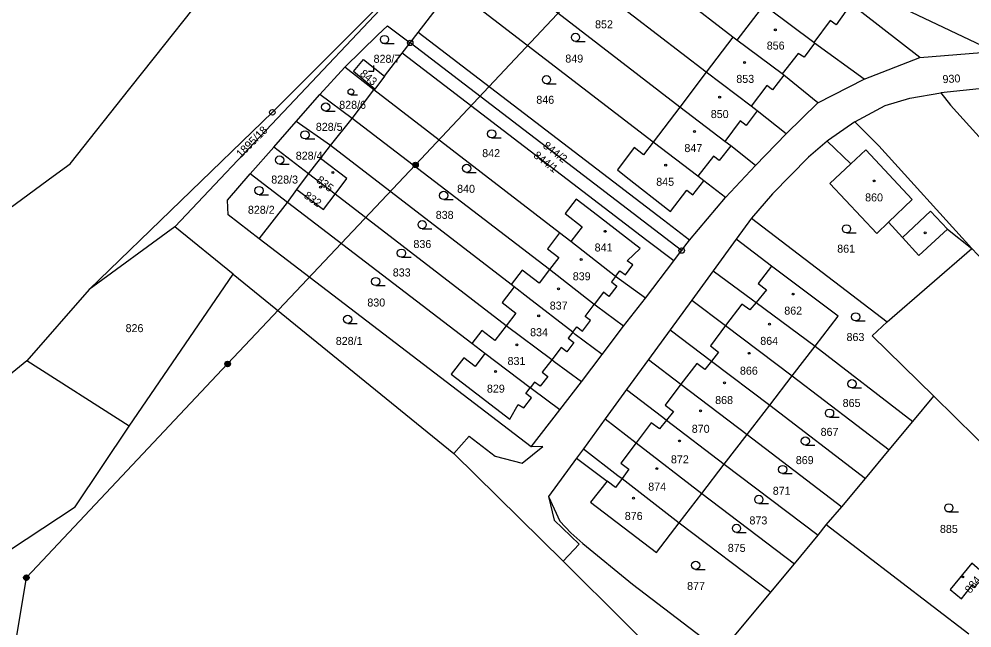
# Model space of a CAD drawing. Extents: x -587171 to -555306, y -1167727 to -1074732.
# Drawn here: x -560459.2 to -560285.3, y -1077700.6 to -1077589.4 of the extents above; entities that cross this region are included whole.
import ezdxf

# ---------------------------------------------------------------- set-up
doc = ezdxf.new("R2010")
doc.units = 0
for name, color, linetype in [('Hranice parcel', 7, 'Continuous'), ('Parcelní čísla', 7, 'Continuous'), ('Poz předměty', 7, 'Continuous'), ('Vnitřní kresba', 7, 'Continuous'), ('Značky bodu BP', 7, 'Continuous'), ('Značky budov', 7, 'Continuous'), ('Značky kultur', 7, 'Continuous')]:
    doc.layers.add(name, color=color, linetype=linetype)

msp = doc.modelspace()

# ---------------------------------------------------------------- linework, layer by layer
at = {"layer": 'Hranice parcel'}
for p, q in [((-560328.96, -1077592.74), (-560364.28, -1077565.15)), ((-560375.85, -1077569.17), (-560430.81, -1077627.37)), ((-560333.83, -1077599.11), (-560365.63, -1077574.69)), ((-560338.65, -1077605.51), (-560374.99, -1077577.45)), ((-560294.85, -1077596.46), (-560316.6, -1077579.54)), ((-560386.37, -1077591.88), (-560380.16, -1077583.81)), ((-560434.49, -1077596.45), (-560425.52, -1077585.14)), ((-560343.49, -1077611.88), (-560376, -1077586.97)), ((-560323.4, -1077586.94), (-560328.26, -1077593.3)), ((-560399.76, -1077598.23), (-560393.77, -1077592.33)), ((-560387.83, -1077593.78), (-560386.37, -1077591.88)), ((-560328.96, -1077592.74), (-560333.83, -1077599.11)), ((-560328.26, -1077593.3), (-560328.96, -1077592.74)), ((-560389.29, -1077595.68), (-560387.83, -1077593.78)), ((-560338.32, -1077631.68), (-560387.83, -1077593.78)), ((-560438.98, -1077602.1), (-560434.49, -1077596.45)), ((-560392.51, -1077599.88), (-560389.29, -1077595.68)), ((-560305.04, -1077600.41), (-560294.85, -1077596.46)), ((-560294.85, -1077596.46), (-560281.21, -1077595.33)), ((-560404.3, -1077603.17), (-560399.76, -1077598.23)), ((-560394.49, -1077602.37), (-560399.76, -1077598.23)), ((-560392.51, -1077599.88), (-560394.27, -1077602.21)), ((-560333.83, -1077599.11), (-560338.65, -1077605.51)), ((-560313.48, -1077604.7), (-560305.04, -1077600.41)), ((-560394.49, -1077602.37), (-560394.27, -1077602.21)), ((-560282.9, -1077602.07), (-560291.02, -1077602.87)), ((-560408.64, -1077608.12), (-560404.3, -1077603.17)), ((-560398.45, -1077607.55), (-560404.3, -1077603.17)), ((-560398.45, -1077607.55), (-560394.49, -1077602.37)), ((-560360.58, -1077628.44), (-560394.49, -1077602.37)), ((-560338.65, -1077605.51), (-560343.49, -1077611.88)), ((-560319.23, -1077610.35), (-560313.48, -1077604.7)), ((-560412.73, -1077612.8), (-560408.64, -1077608.12)), ((-560402.41, -1077612.48), (-560408.64, -1077608.12)), ((-560402.41, -1077612.48), (-560398.45, -1077607.55)), ((-560362.45, -1077635.15), (-560398.45, -1077607.55)), ((-560324.82, -1077616.15), (-560319.23, -1077610.35)), ((-560404.23, -1077614.85), (-560402.41, -1077612.48)), ((-560369.4, -1077637.89), (-560402.41, -1077612.48)), ((-560417.03, -1077617.7), (-560412.73, -1077612.8)), ((-560406.38, -1077617.66), (-560412.73, -1077612.8)), ((-560406.38, -1077617.66), (-560404.23, -1077614.85)), ((-560330.32, -1077621.99), (-560324.82, -1077616.15)), ((-560421.2, -1077622.46), (-560417.03, -1077617.7)), ((-560410.21, -1077622.9), (-560417.03, -1077617.7)), ((-560408.5, -1077620.55), (-560406.38, -1077617.66)), ((-560401.53, -1077621.39), (-560406.38, -1077617.66)), ((-560471.23, -1077631.45), (-560452.96, -1077618.09)), ((-560330.32, -1077621.99), (-560334.28, -1077618.93)), ((-560410.21, -1077622.9), (-560408.5, -1077620.55)), ((-560370.31, -1077645.39), (-560401.53, -1077621.39)), ((-560415.38, -1077629.52), (-560410.21, -1077622.9)), ((-560376.61, -1077648.66), (-560410.21, -1077622.9)), ((-560336.89, -1077629.78), (-560330.32, -1077621.99)), ((-560325.56, -1077625.77), (-560328.38, -1077629.63)), ((-560325.56, -1077625.77), (-560300.82, -1077644.66)), ((-560430.81, -1077627.37), (-560446.42, -1077638.81)), ((-560420.13, -1077636.01), (-560430.81, -1077627.37)), ((-560365.79, -1077667.51), (-560415.38, -1077629.52)), ((-560358.52, -1077630.03), (-560360.58, -1077628.44)), ((-560350.37, -1077636.41), (-560358.52, -1077630.03)), ((-560338.32, -1077631.68), (-560336.89, -1077629.78)), ((-560328.38, -1077629.63), (-560332.57, -1077635.37)), ((-560339.72, -1077633.58), (-560338.32, -1077631.68)), ((-560300.82, -1077644.66), (-560285.36, -1077631.28)), ((-560344.89, -1077640.37), (-560339.72, -1077633.58)), ((-560439.14, -1077663.72), (-560420.13, -1077636.01)), ((-560420.13, -1077636.01), (-560379.89, -1077668.73)), ((-560344.89, -1077640.37), (-560350.37, -1077636.41)), ((-560332.57, -1077635.37), (-560336.47, -1077640.72)), ((-560368.85, -1077638.32), (-560369.4, -1077637.89)), ((-560446.42, -1077638.81), (-560457.78, -1077651.79)), ((-560348.9, -1077645.47), (-560344.89, -1077640.37)), ((-560336.47, -1077640.72), (-560340.42, -1077646.14)), ((-560352.79, -1077650.67), (-560348.9, -1077645.47)), ((-560340.42, -1077646.14), (-560344.39, -1077651.58)), ((-560374.22, -1077650.49), (-560376.61, -1077648.66)), ((-560318.12, -1077654.53), (-560313.97, -1077649.13)), ((-560313.97, -1077649.13), (-560296.15, -1077662.88)), ((-560365.96, -1077656.73), (-560374.22, -1077650.49)), ((-560356.61, -1077655.66), (-560352.79, -1077650.67)), ((-560439.14, -1077663.72), (-560457.78, -1077651.79)), ((-560344.39, -1077651.58), (-560348.35, -1077657.02)), ((-560360.53, -1077660.72), (-560356.61, -1077655.66)), ((-560322.24, -1077659.89), (-560318.12, -1077654.53)), ((-560318.12, -1077654.53), (-560300.47, -1077668.07)), ((-560348.35, -1077657.02), (-560352.28, -1077662.4)), ((-560296.15, -1077662.88), (-560292.32, -1077658.28)), ((-560365.79, -1077667.51), (-560360.53, -1077660.72)), ((-560326.37, -1077665.27), (-560322.24, -1077659.89)), ((-560322.24, -1077659.89), (-560304.79, -1077673.26)), ((-560352.28, -1077662.4), (-560356.25, -1077667.84)), ((-560300.47, -1077668.07), (-560296.15, -1077662.88)), ((-560330.53, -1077670.68), (-560326.37, -1077665.27)), ((-560326.37, -1077665.27), (-560309.1, -1077678.45)), ((-560356.25, -1077667.84), (-560357.49, -1077669.54)), ((-560304.79, -1077673.26), (-560300.47, -1077668.07)), ((-560379.89, -1077668.73), (-560359.92, -1077688.39)), ((-560357.49, -1077669.54), (-560362.63, -1077676.58)), ((-560334.63, -1077676), (-560330.53, -1077670.68)), ((-560330.53, -1077670.68), (-560313.42, -1077683.64)), ((-560309.1, -1077678.45), (-560304.79, -1077673.26)), ((-560338.75, -1077681.37), (-560334.63, -1077676)), ((-560334.63, -1077676), (-560317.73, -1077688.83)), ((-560311.93, -1077681.72), (-560309.1, -1077678.45)), ((-560338.75, -1077681.37), (-560322.05, -1077694.02)), ((-560313.42, -1077683.64), (-560311.93, -1077681.72)), ((-560285.91, -1077701.68), (-560311.93, -1077681.72)), ((-560317.73, -1077688.83), (-560313.42, -1077683.64)), ((-560322.05, -1077694.02), (-560317.73, -1077688.83)), ((-560331.1, -1077704.9), (-560322.05, -1077694.02))]:
    msp.add_line(p, q, dxfattribs=at)
for points in [[(-560375.85, -1077569.17), (-560412.99, -1077606.45), (-560446.42, -1077638.81)], [(-560312.4, -1077568.89), (-560315.15, -1077573.69), (-560305.39, -1077581.46), (-560297.55, -1077587.6), (-560281.21, -1077595.33)], [(-560305.04, -1077600.41), (-560314.06, -1077593.83), (-560314.2, -1077593.72), (-560322.61, -1077587.46)], [(-560393.77, -1077592.33), (-560391.98, -1077590.67), (-560387.83, -1077593.78)], [(-560336.89, -1077629.78), (-560341.64, -1077626.13), (-560386.37, -1077591.88)], [(-560313.48, -1077604.7), (-560319.68, -1077599.65), (-560319.95, -1077599.45), (-560328.26, -1077593.3)], [(-560394.27, -1077602.21), (-560398.2, -1077599.02), (-560396.35, -1077596.84), (-560392.51, -1077599.88)], [(-560339.72, -1077633.58), (-560344.65, -1077629.82), (-560389.29, -1077595.68)], [(-560319.23, -1077610.35), (-560324.55, -1077606.15), (-560325.65, -1077605.33), (-560333.83, -1077599.11)], [(-560452.96, -1077618.09), (-560449.89, -1077615.85), (-560438.98, -1077602.1)], [(-560306.74, -1077608.21), (-560301.16, -1077605.22), (-560296.7, -1077603.88), (-560291.02, -1077602.87)], [(-560291.02, -1077602.87), (-560289.24, -1077605.17), (-560274.76, -1077621.16), (-560270.12, -1077616.52)], [(-560324.82, -1077616.15), (-560329.36, -1077612.58), (-560330.46, -1077611.76), (-560338.65, -1077605.51)], [(-560306.74, -1077608.21), (-560311.54, -1077611.52), (-560311.77, -1077611.71)], [(-560285.36, -1077631.28), (-560302.35, -1077612.59), (-560306.74, -1077608.21)], [(-560343.49, -1077611.88), (-560345.29, -1077614.19), (-560346.96, -1077612.89), (-560350.02, -1077616.95), (-560348.41, -1077618.21), (-560340.34, -1077624.54), (-560337.38, -1077620.65), (-560336.25, -1077621.5), (-560334.28, -1077618.93)], [(-560334.28, -1077618.93), (-560335.35, -1077618.1), (-560343.49, -1077611.88)], [(-560311.77, -1077611.71), (-560315.2, -1077614.66), (-560321.76, -1077621.32), (-560325.56, -1077625.77)], [(-560311.77, -1077611.71), (-560307.44, -1077615.83), (-560311.29, -1077619.43), (-560302.73, -1077628.55), (-560300.57, -1077626.48), (-560298, -1077629.32), (-560295.01, -1077632.56), (-560289.83, -1077627.79), (-560285.36, -1077631.28)], [(-560401.53, -1077621.39), (-560399.42, -1077618.53), (-560404.23, -1077614.85)], [(-560408.5, -1077620.55), (-560403.64, -1077624.21), (-560401.53, -1077621.39)], [(-560415.38, -1077629.52), (-560421.06, -1077625.15), (-560421.2, -1077622.46)], [(-560350.37, -1077636.41), (-560349.58, -1077635.36), (-560348.58, -1077636.12), (-560347.22, -1077634.29), (-560348.25, -1077633.54), (-560345.86, -1077631.3), (-560354.43, -1077624.7), (-560357.56, -1077622.29), (-560359.58, -1077624.92), (-560356.44, -1077627.33), (-560358.52, -1077630.03)], [(-560360.58, -1077628.44), (-560362.77, -1077631.37), (-560360.74, -1077632.93), (-560362.45, -1077635.15)], [(-560313.97, -1077649.13), (-560309.75, -1077643.64), (-560321.91, -1077634.5), (-560328.38, -1077629.63)], [(-560281.82, -1077635.16), (-560283.33, -1077633.51), (-560285.36, -1077631.28)], [(-560362.45, -1077635.15), (-560364.34, -1077637.62), (-560367.4, -1077635.27), (-560369.4, -1077637.89)], [(-560348.9, -1077645.47), (-560353.88, -1077641.83), (-560354.28, -1077641.52), (-560362.45, -1077635.15)], [(-560332.57, -1077635.37), (-560325.38, -1077640.68), (-560324.74, -1077641.16), (-560313.97, -1077649.13)], [(-560368.85, -1077638.32), (-560371.04, -1077641.16), (-560368.54, -1077643.08), (-560370.31, -1077645.39)], [(-560352.79, -1077650.67), (-560357.73, -1077646.97), (-560358.19, -1077646.6), (-560366.35, -1077640.24), (-560368.85, -1077638.32)], [(-560336.47, -1077640.72), (-560330.3, -1077645.36), (-560318.12, -1077654.53)], [(-560370.31, -1077645.39), (-560372.39, -1077648.11), (-560374.78, -1077646.28), (-560376.61, -1077648.66)], [(-560356.61, -1077655.66), (-560361.56, -1077651.96), (-560362.01, -1077651.62), (-560370.31, -1077645.39)], [(-560292.32, -1077658.28), (-560303.56, -1077647.23), (-560300.82, -1077644.66)], [(-560340.42, -1077646.14), (-560332.85, -1077651.86), (-560322.24, -1077659.89)], [(-560374.22, -1077650.49), (-560376.01, -1077652.83), (-560378.08, -1077651.24), (-560380.39, -1077654.25), (-560378.32, -1077655.83), (-560369.68, -1077662.43), (-560368.13, -1077659.77), (-560367.08, -1077660.38), (-560365.72, -1077658.55), (-560366.75, -1077657.77), (-560365.96, -1077656.73)], [(-560457.78, -1077651.79), (-560466.53, -1077658.92), (-560480.72, -1077671.61), (-560494.34, -1077686.1), (-560508.9, -1077703.53)], [(-560344.39, -1077651.58), (-560338.46, -1077656.08), (-560326.37, -1077665.27)], [(-560360.53, -1077660.72), (-560365.51, -1077657.06), (-560365.96, -1077656.73)], [(-560348.35, -1077657.02), (-560341.74, -1077662.09), (-560341.05, -1077662.62), (-560330.53, -1077670.68)], [(-560237.94, -1077711.73), (-560238.65, -1077711.03), (-560292.32, -1077658.28)], [(-560352.28, -1077662.4), (-560346.63, -1077666.75), (-560334.63, -1077676)], [(-560498.51, -1077705.52), (-560481.85, -1077698.21), (-560474.04, -1077694.55), (-560466.89, -1077690.27), (-560448.98, -1077678.42), (-560439.14, -1077663.72)], [(-560379.89, -1077668.73), (-560377.06, -1077665.55), (-560372.31, -1077669.2), (-560367.44, -1077670.51), (-560363.63, -1077667.44), (-560365.79, -1077667.51)], [(-560356.25, -1077667.84), (-560349.94, -1077672.72), (-560349.19, -1077673.3), (-560338.75, -1077681.37)], [(-560357.49, -1077669.54), (-560351.9, -1077673.74), (-560354.93, -1077677.6), (-560342.93, -1077686.8), (-560338.75, -1077681.37)], [(-560362.63, -1077676.58), (-560360.56, -1077681.04), (-560358.52, -1077683.18), (-560356.35, -1077685.14), (-560347.27, -1077692.56), (-560331.1, -1077704.9)], [(-560362.63, -1077676.58), (-560361.55, -1077680.87), (-560357.03, -1077685.24), (-560359.92, -1077688.39)], [(-560359.92, -1077688.39), (-560336.97, -1077711.25), (-560277.37, -1077755.62)], [(-560284.85, -1077693.05), (-560282.89, -1077690.9), (-560285.37, -1077688.75), (-560289.35, -1077693.54), (-560287.27, -1077695.26), (-560285.22, -1077692.71), (-560284.85, -1077693.05)]]:
    msp.add_lwpolyline(points, dxfattribs=at)
at = {"layer": 'Poz předměty'}
for p, q in [((-560354.12, -1077581.15), (-560386.86, -1077616.04)), ((-560386.86, -1077616.04), (-560421.15, -1077652.37)), ((-560457.87, -1077691.37), (-560421.15, -1077652.37)), ((-560467.98, -1077753.51), (-560457.87, -1077691.37))]:
    msp.add_line(p, q, dxfattribs=at)
for centre, radius in [((-560386.86, -1077616.04), 0.5), ((-560386.86, -1077616.04), 0.4), ((-560386.86, -1077616.04), 0.3), ((-560386.86, -1077616.04), 0.2), ((-560386.86, -1077616.04), 0.1), ((-560421.15, -1077652.37), 0.5), ((-560421.15, -1077652.37), 0.5), ((-560421.15, -1077652.37), 0.4), ((-560421.15, -1077652.37), 0.4), ((-560421.15, -1077652.37), 0.3), ((-560421.15, -1077652.37), 0.3), ((-560421.15, -1077652.37), 0.2), ((-560421.15, -1077652.37), 0.2), ((-560421.15, -1077652.37), 0.1), ((-560421.15, -1077652.37), 0.1), ((-560457.87, -1077691.37), 0.5), ((-560457.87, -1077691.37), 0.4), ((-560457.87, -1077691.37), 0.3), ((-560457.87, -1077691.37), 0.2), ((-560457.87, -1077691.37), 0.1)]:
    msp.add_circle(centre, radius, dxfattribs=at)
at = {"layer": 'Vnitřní kresba'}
for p, q in [((-560308.34, -1077588), (-560310.13, -1077590.48)), ((-560311.2, -1077589.68), (-560314.2, -1077593.72)), ((-560310.13, -1077590.48), (-560311.2, -1077589.68)), ((-560314.06, -1077593.83), (-560315.98, -1077596.41)), ((-560317.06, -1077595.71), (-560319.95, -1077599.45)), ((-560315.98, -1077596.41), (-560317.06, -1077595.71)), ((-560319.68, -1077599.65), (-560321.74, -1077602.35)), ((-560322.8, -1077601.56), (-560325.65, -1077605.33)), ((-560321.74, -1077602.35), (-560322.8, -1077601.56)), ((-560324.55, -1077606.15), (-560326.53, -1077608.83)), ((-560327.64, -1077608), (-560330.46, -1077611.76)), ((-560326.53, -1077608.83), (-560327.64, -1077608)), ((-560329.36, -1077612.58), (-560331.45, -1077615.27)), ((-560307.44, -1077615.83), (-560304.74, -1077613.31)), ((-560304.74, -1077613.31), (-560296.27, -1077622.39)), ((-560332.52, -1077614.44), (-560335.35, -1077618.1)), ((-560331.45, -1077615.27), (-560332.52, -1077614.44)), ((-560296.27, -1077622.39), (-560300.57, -1077626.48)), ((-560292.92, -1077624.51), (-560298, -1077629.32)), ((-560292.92, -1077624.51), (-560289.83, -1077627.79)), ((-560321.91, -1077634.5), (-560324.34, -1077637.72)), ((-560350.37, -1077636.41), (-560351.12, -1077637.39)), ((-560350.13, -1077638.15), (-560351.58, -1077640.04)), ((-560351.12, -1077637.39), (-560350.13, -1077638.15)), ((-560324.34, -1077637.72), (-560322.81, -1077638.87)), ((-560352.58, -1077639.29), (-560354.28, -1077641.52)), ((-560351.58, -1077640.04), (-560352.58, -1077639.29)), ((-560322.81, -1077638.87), (-560324.74, -1077641.16)), ((-560355.94, -1077643.71), (-560354.28, -1077641.52)), ((-560327.31, -1077641.44), (-560330.3, -1077645.36)), ((-560325.88, -1077642.51), (-560327.31, -1077641.44)), ((-560324.74, -1077641.16), (-560325.88, -1077642.51)), ((-560354.94, -1077644.47), (-560355.94, -1077643.71)), ((-560358.19, -1077646.6), (-560357.43, -1077645.61)), ((-560357.43, -1077645.61), (-560356.39, -1077646.41)), ((-560356.39, -1077646.41), (-560354.94, -1077644.47)), ((-560330.3, -1077645.36), (-560333.07, -1077649.09)), ((-560358.19, -1077646.6), (-560359.02, -1077647.68)), ((-560357.99, -1077648.47), (-560359.27, -1077650.16)), ((-560359.02, -1077647.68), (-560357.99, -1077648.47)), ((-560333.07, -1077649.09), (-560331.57, -1077650.22)), ((-560360.3, -1077649.38), (-560362.01, -1077651.62)), ((-560359.27, -1077650.16), (-560360.3, -1077649.38)), ((-560331.57, -1077650.22), (-560332.85, -1077651.86)), ((-560362.01, -1077651.62), (-560363.75, -1077653.9)), ((-560335.56, -1077652.27), (-560338.46, -1077656.08)), ((-560334.07, -1077653.41), (-560335.56, -1077652.27)), ((-560332.85, -1077651.86), (-560334.07, -1077653.41)), ((-560363.75, -1077653.9), (-560362.74, -1077654.66)), ((-560365.16, -1077655.67), (-560365.96, -1077656.73)), ((-560364.14, -1077656.44), (-560365.16, -1077655.67)), ((-560362.74, -1077654.66), (-560364.14, -1077656.44)), ((-560338.46, -1077656.08), (-560341.33, -1077659.87)), ((-560341.33, -1077659.87), (-560339.8, -1077661.04)), ((-560339.8, -1077661.04), (-560341.05, -1077662.62)), ((-560343.86, -1077663.09), (-560346.63, -1077666.75)), ((-560342.33, -1077664.23), (-560343.86, -1077663.09)), ((-560341.05, -1077662.62), (-560342.33, -1077664.23)), ((-560346.63, -1077666.75), (-560349.41, -1077670.49)), ((-560349.41, -1077670.49), (-560347.93, -1077671.6)), ((-560347.93, -1077671.6), (-560349.19, -1077673.3)), ((-560349.19, -1077673.3), (-560350.39, -1077674.93)), ((-560350.39, -1077674.93), (-560351.9, -1077673.74))]:
    msp.add_line(p, q, dxfattribs=at)
at = {"layer": 'Značky bodu BP'}
for centre, radius in [((-560387.83, -1077593.78), 0.5), ((-560387.83, -1077593.78), 0.0303), ((-560412.99, -1077606.45), 0.5), ((-560412.99, -1077606.45), 0.0303), ((-560338.32, -1077631.68), 0.5), ((-560338.32, -1077631.68), 0.0303)]:
    msp.add_circle(centre, radius, dxfattribs=at)
at = {"layer": 'Značky budov'}
for centre in [(-560321.22, -1077591.39), (-560326.82, -1077597.38), (-560331.38, -1077603.68), (-560335.96, -1077609.96), (-560341.23, -1077616.11), (-560401.93, -1077617.42), (-560303.18, -1077618.98), (-560404.19, -1077620.12), (-560352.27, -1077628.17), (-560293.87, -1077628.44), (-560356.63, -1077633.33), (-560360.77, -1077638.66), (-560317.95, -1077639.61), (-560364.4, -1077643.58), (-560322.28, -1077645.11), (-560368.36, -1077648.87), (-560325.99, -1077650.43), (-560372.25, -1077653.77), (-560330.51, -1077655.81), (-560334.85, -1077660.91), (-560338.72, -1077666.43), (-560342.83, -1077671.48), (-560347.08, -1077676.89), (-560287.04, -1077691.25)]:
    msp.add_circle(centre, 0.175, dxfattribs=at)
at = {"layer": 'Značky kultur'}
for p, q in [((-560357.68, -1077593.52), (-560355.93, -1077593.52)), ((-560392.53, -1077593.92), (-560390.78, -1077593.92)), ((-560394.46, -1077598.92), (-560394.46, -1077597.92)), ((-560395.46, -1077598.92), (-560394.46, -1077598.92)), ((-560362.98, -1077601.25), (-560361.23, -1077601.25)), ((-560398.66, -1077603.23), (-560397.43, -1077603.23)), ((-560403.27, -1077606.24), (-560401.52, -1077606.24)), ((-560407.02, -1077611.31), (-560405.27, -1077611.31)), ((-560372.99, -1077611.12), (-560371.24, -1077611.12)), ((-560411.67, -1077615.91), (-560409.92, -1077615.91)), ((-560377.54, -1077617.43), (-560375.79, -1077617.43)), ((-560415.42, -1077621.48), (-560413.67, -1077621.48)), ((-560381.73, -1077622.37), (-560379.98, -1077622.37)), ((-560385.65, -1077627.7), (-560383.9, -1077627.7)), ((-560308.24, -1077628.46), (-560306.49, -1077628.46)), ((-560389.44, -1077632.91), (-560387.69, -1077632.91)), ((-560394.13, -1077638.08), (-560392.38, -1077638.08)), ((-560399.24, -1077644.97), (-560397.49, -1077644.97)), ((-560306.57, -1077644.53), (-560304.82, -1077644.53)), ((-560307.24, -1077656.74), (-560305.49, -1077656.74)), ((-560311.33, -1077662.11), (-560309.58, -1077662.11)), ((-560315.74, -1077667.2), (-560313.99, -1077667.2)), ((-560319.89, -1077672.38), (-560318.14, -1077672.38)), ((-560324.23, -1077677.85), (-560322.48, -1077677.85)), ((-560289.57, -1077679.39), (-560287.82, -1077679.39)), ((-560328.31, -1077683.13), (-560326.56, -1077683.13)), ((-560335.76, -1077689.87), (-560334.01, -1077689.87))]:
    msp.add_line(p, q, dxfattribs=at)
for centre, radius in [((-560392.53, -1077593.17), 0.75), ((-560357.68, -1077592.77), 0.75), ((-560362.98, -1077600.5), 0.75), ((-560398.66, -1077602.7), 0.525), ((-560403.27, -1077605.49), 0.75), ((-560407.02, -1077610.56), 0.75), ((-560372.99, -1077610.37), 0.75), ((-560411.67, -1077615.16), 0.75), ((-560377.54, -1077616.68), 0.75), ((-560415.42, -1077620.73), 0.75), ((-560381.73, -1077621.62), 0.75), ((-560385.65, -1077626.95), 0.75), ((-560308.24, -1077627.71), 0.75), ((-560389.44, -1077632.16), 0.75), ((-560394.13, -1077637.33), 0.75), ((-560399.24, -1077644.22), 0.75), ((-560306.57, -1077643.78), 0.75), ((-560307.24, -1077655.99), 0.75), ((-560311.33, -1077661.36), 0.75), ((-560315.74, -1077666.45), 0.75), ((-560319.89, -1077671.63), 0.75), ((-560324.23, -1077677.1), 0.75), ((-560289.57, -1077678.64), 0.75), ((-560328.31, -1077682.38), 0.75), ((-560335.76, -1077689.12), 0.75)]:
    msp.add_circle(centre, radius, dxfattribs=at)

# ---------------------------------------------------------------- texts
at = {"layer": 'Parcelní čísla'}
for s, p in [('852', (-560354.11, -1077591.12)), ('856', (-560322.79, -1077595)), ('828/7', (-560394.52, -1077597.41)), ('849', (-560359.54, -1077597.37)), ('853', (-560328.34, -1077601.08)), ('846', (-560364.83, -1077604.89)), ('828/6', (-560400.79, -1077605.81)), ('850', (-560333, -1077607.5)), ('828/5', (-560405.06, -1077609.83)), ('847', (-560337.81, -1077613.71)), ('828/4', (-560408.72, -1077615.09)), ('842', (-560374.7, -1077614.63)), ('828/3', (-560413.19, -1077619.45)), ('845', (-560342.95, -1077619.86)), ('840', (-560379.28, -1077621.14)), ('860', (-560304.84, -1077622.71)), ('828/2', (-560417.45, -1077624.97)), ('838', (-560383.18, -1077625.9)), ('836', (-560387.25, -1077631.22)), ('841', (-560354.19, -1077631.85)), ('861', (-560309.93, -1077632.07)), ('833', (-560391.02, -1077636.41)), ('839', (-560358.18, -1077637.1)), ('830', (-560395.66, -1077641.89)), ('837', (-560362.38, -1077642.45)), ('862', (-560319.59, -1077643.37)), ('826', (-560439.77, -1077646.57)), ('828/1', (-560401.42, -1077648.9)), ('834', (-560365.96, -1077647.31)), ('864', (-560323.97, -1077648.89)), ('863', (-560308.23, -1077648.19)), ('831', (-560370.08, -1077652.56)), ('866', (-560327.68, -1077654.33)), ('829', (-560373.84, -1077657.61)), ('868', (-560332.2, -1077659.69)), ('865', (-560308.94, -1077660.22)), ('870', (-560336.47, -1077664.94)), ('867', (-560312.96, -1077665.5)), ('872', (-560340.27, -1077670.51)), ('869', (-560317.49, -1077670.65)), ('874', (-560344.41, -1077675.49)), ('871', (-560321.69, -1077676.25)), ('876', (-560348.69, -1077680.84)), ('873', (-560325.94, -1077681.66)), ('885', (-560291.19, -1077683.21)), ('875', (-560329.9, -1077686.67)), ('877', (-560337.32, -1077693.62))]:
    msp.add_text(s, height=1.46, dxfattribs=at).set_placement(p)
for s, rotation, p in [('843', 321, (-560397.15, -1077599.63)), ('930', 3, (-560290.68, -1077601.14)), ('1895/18', 45, (-560418.72, -1077614.84)), ('844/2', 322, (-560363.75, -1077612.78)), ('844/1', 322, (-560365.47, -1077614.56)), ('835', 321, (-560405.1, -1077619.04)), ('832', 325, (-560407.35, -1077621.95)), ('884', 51, (-560285.66, -1077694.36))]:
    msp.add_text(s, height=1.46, rotation=rotation, dxfattribs=at).set_placement(p)

doc.saveas('drawing.dxf')
